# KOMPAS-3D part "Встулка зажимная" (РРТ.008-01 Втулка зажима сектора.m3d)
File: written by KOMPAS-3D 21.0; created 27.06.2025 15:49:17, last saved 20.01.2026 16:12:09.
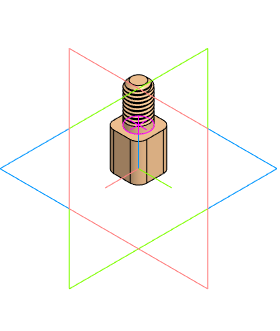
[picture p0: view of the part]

Document properties: Полное имя файла: C:\Users\Alexey\Documents\Bitrix24\Производство\технологии\KazanTarget\эксперименты\ручной ротатор\РРТ.008-01 Втулка зажима сектора\РРТ.008 Втулка зажима сектора.m3d; Автор: User

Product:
- Part/product: Встулка зажимная
    Масса: 0.01914
    Форматы листов документа: A4

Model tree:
1. Эскиз:2
2. Элемент выдавливания:1
     Расстояние 1 = 13.6
3. Скругление:1  (with: Элемент выдавливания:1)
     Радиус = 3
4. Эскиз:3  (with: Элемент выдавливания:1)
5. Элемент выдавливания:2  (with: ЛСК (Внешняя цилиндрическая ступень с метрической резьбой):1, Внешняя цилиндрическая ступень с метрической резьбой:1, Плоскость XY, Плоскость ZX, Плоскость ZY, Ось X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)
     Расстояние 1 = 2; Ось X. Z = -1; Ось Y. X = -1; Ось Z. Y = 1; Точка начала. Z = 15.6; Угол 1 = 360; Угол 1 = 360; Угол 1 = 360
6. Эскиз выреза профиля резьбы (Внешняя цилиндрическая ступень с метрической резьбой):1  (with: Винтовая линия (Внешняя цилиндрическая ступень с метрической резьбой):1, Булева операция:1)
     Расстояние = 12; Число витков = 9.6; Шаг = 1.25; Высота = 12; Диаметр 1 = 8; Диаметр 2 = 10; Угол = 270; Число витков = 2.5; Шаг = 1.25; Высота = 3.125; Диаметр 1 = 8; Диаметр 2 = 10.5252; Угол наклона образующей = 22; Угол = 54
7. Внешняя цилиндрическая ступень с метрической резьбой:1

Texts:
  [Data]  D=8  L=12  Len_Th=12  Step=1.25  Tip_Step=1  PoleTh=[6g]  Flag_Left_Thread=2  ExistThrough=0  TypeThrough=1  SubType=0  DiamF=0  Flag_FaskOnGOST=1  Fask=1.6  FAngle=45  F=4  R=1  R1=0.5  R2=0  Df=1.8  Flag_NoStandart=2  NS_Prototype=0  NTDThrough=0  MarkRing=N  MarkThread=М8-6g
  SHAFT3D
  (VCThMetrO_1_D<=0||VCThMetrO_1_D>5e+7)?25:VCThMetrO_1_D
  (VCThMetrO_1_L<=0||VCThMetrO_1_L>5e+7)?25:VCThMetrO_1_L
  Плоскость начала спирали резьбы (Внешняя цилиндрическая ступень с метрической резьбой):1
  Эскиз для винтовой линии (Внешняя цилиндрическая ступень с метрической резьбой):1
  Плоскость начала конической спирали резьбы (Внешняя цилиндрическая ступень с метрической резьбой):1
  Коническая винтовая линия (Внешняя цилиндрическая ступень с метрической резьбой):1
  Вырез профиля резьбы (Внешняя цилиндрическая ступень с метрической резьбой):1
